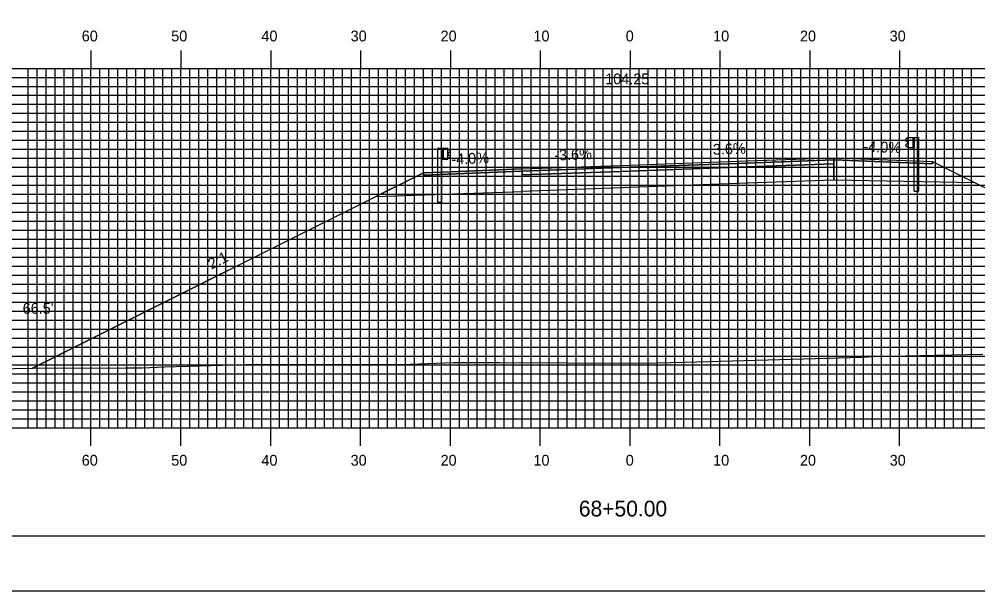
# Model space of a CAD drawing. Extents: x 1759823 to 1760167, y 442591 to 442811.
# Drawn here: x 1759921.2 to 1760027.9, y 442590.5 to 442654.1 of the extents above; entities that cross this region are included whole.
import ezdxf

# ---------------------------------------------------------------- set-up
doc = ezdxf.new("R2010")
doc.units = 0
for name, color, linetype in [('ANNOTATION', 7, 'Continuous'), ('BORDER', 7, 'Continuous'), ('D_Guardrail_Beam_Lt', 7, 'Continuous'), ('D_Guardrail_Beam_Rt', 7, 'Continuous'), ('D_Roadway_Centerline', 7, 'Continuous'), ('D_Roadway_Centerline_Text', 7, 'Continuous'), ('D_Roadway_Edge_Shoulder', 7, 'Continuous'), ('D_Roadway_Edge_TW', 7, 'Continuous'), ('D_Roadway_Pavement', 7, 'Continuous'), ('D_Roadway_SlopeLines', 7, 'Continuous'), ('D_Roadway_SubGrade', 7, 'Continuous'), ('D_Text_Standard', 7, 'Continuous'), ('H_V ANNOTATION', 7, 'Continuous'), ('MAJOR', 7, 'Continuous'), ('MINOR', 7, 'Continuous'), ('PLOT BOUNDARY', 7, 'Continuous'), ('S_Roadway_Centerline', 7, 'Continuous')]:
    doc.layers.add(name, color=color, linetype=linetype)

msp = doc.modelspace()

# ---------------------------------------------------------------- linework, layer by layer
at = {"layer": 'BORDER'}
msp.add_lwpolyline([(1759839.59, 442596.67), (1760159.59, 442596.67), (1760159.59, 442806.67), (1759839.59, 442806.67)], close=True, dxfattribs=at)
at = {"layer": 'D_Guardrail_Beam_Lt'}
for p, q in [((1759967.76, 442639.75), (1759967.76, 442633.75)), ((1759968.23, 442639.75), (1759967.76, 442639.75)), ((1759968.92, 442639.75), (1759968.23, 442639.75)), ((1759968.23, 442639.75), (1759968.23, 442638.58)), ((1759968.29, 442639.75), (1759968.29, 442638.58)), ((1759968.4, 442639.75), (1759968.4, 442638.58)), ((1759968.92, 442638.58), (1759968.92, 442639.75)), ((1759968.92, 442639.66), (1759968.99, 442639.65)), ((1759968.92, 442639.2), (1759968.92, 442639.13)), ((1759969.15, 442639.4), (1759968.95, 442639.26)), ((1759968.95, 442639.06), (1759969.15, 442638.93)), ((1759969.01, 442639.64), (1759969.15, 442639.54)), ((1759968.23, 442638.58), (1759968.92, 442638.58)), ((1759968.25, 442633.75), (1759968.25, 442638.58)), ((1759968.99, 442638.68), (1759968.92, 442638.66)), ((1759969.15, 442638.78), (1759969.01, 442638.68)), ((1759968.25, 442633.75), (1759967.76, 442633.75))]:
    msp.add_line(p, q, dxfattribs=at)
for centre, major_axis, start_param, end_param in [((1759969, 442639.2), (-0.0789, 0), 5.323254, 6.283185), ((1759969, 442639.13), (-0.0789, 0), 6.283185, 7.243116), ((1759968.98, 442639.61), (0.0417, 0), 0.959931, 1.376053), ((1759969.1, 442639.47), (0.0877, 0), 5.323254, 7.243116), ((1759968.98, 442638.72), (0.0417, 0), 4.907132, 5.323254), ((1759969.1, 442638.86), (0.0877, 0), 5.323254, 7.243116)]:
    msp.add_ellipse(centre, major_axis=major_axis, ratio=0.995501, start_param=start_param, end_param=end_param, dxfattribs=at)
at = {"layer": 'D_Guardrail_Beam_Rt'}
for p, q in [((1760020.04, 442640.89), (1760019.9, 442640.79)), ((1760019.9, 442640.65), (1760020.09, 442640.51)), ((1760020.09, 442640.31), (1760019.9, 442640.18)), ((1760020.13, 442640.91), (1760020.06, 442640.9)), ((1760020.13, 442640.99), (1760020.82, 442640.99)), ((1760020.13, 442639.83), (1760020.13, 442640.99)), ((1760020.13, 442640.45), (1760020.13, 442640.38)), ((1760020.65, 442640.99), (1760020.65, 442639.83)), ((1760020.76, 442640.99), (1760020.76, 442639.83)), ((1760020.82, 442640.99), (1760021.29, 442640.99)), ((1760020.82, 442640.99), (1760020.82, 442639.83)), ((1760021.29, 442640.99), (1760021.29, 442634.99)), ((1760019.9, 442640.03), (1760020.04, 442639.93)), ((1760020.06, 442639.93), (1760020.13, 442639.91)), ((1760020.82, 442639.83), (1760020.13, 442639.83)), ((1760020.8, 442634.99), (1760020.8, 442639.83)), ((1760020.8, 442634.99), (1760021.29, 442634.99))]:
    msp.add_line(p, q, dxfattribs=at)
for centre, major_axis, start_param, end_param in [((1760019.95, 442640.72), (-0.0877, 0), 5.323254, 7.243116), ((1760019.95, 442640.1), (-0.0877, 0), 5.323254, 7.243116), ((1760020.07, 442640.86), (-0.0417, 0), 4.907132, 5.323254), ((1760020.05, 442640.45), (0.0789, 0), 0, 0.959931), ((1760020.05, 442640.38), (0.0789, 0), 5.323254, 6.283185), ((1760020.07, 442639.97), (-0.0417, 0), 0.959931, 1.376053)]:
    msp.add_ellipse(centre, major_axis=major_axis, ratio=0.995501, start_param=start_param, end_param=end_param, dxfattribs=at)
at = {"layer": 'D_Roadway_Centerline'}
msp.add_lwpolyline([(1759922.69, 442615.3), (1759960.89, 442634.4), (1759966.19, 442637.04), (1759969.19, 442637.16), (1759977.19, 442637.48), (1759989.19, 442637.91), (1760001.19, 442638.35), (1760011.86, 442638.73), (1760019.86, 442638.41), (1760022.86, 442638.29), (1760027.61, 442635.92), (1760064.16, 442617.64)], dxfattribs=at)
at = {"layer": 'D_Roadway_Edge_Shoulder'}
for points in [[(1760011.86, 442638.73), (1760019.86, 442638.41), (1760019.86, 442638.41), (1760022.86, 442638.29), (1760022.86, 442638.04), (1760011.86, 442638.48)], [(1759977.19, 442637.48), (1759969.19, 442637.16), (1759969.19, 442637.16), (1759966.19, 442637.04), (1759966.19, 442636.79), (1759977.19, 442637.23)]]:
    msp.add_lwpolyline(points, close=True, dxfattribs=at)
at = {"layer": 'D_Roadway_Edge_TW'}
for points in [[(1759977.19, 442637.23), (1759977.19, 442637.48), (1759989.19, 442637.91), (1760001.19, 442638.35), (1760001.19, 442638.1), (1759989.19, 442637.66)], [(1760001.19, 442638.35), (1760011.86, 442638.73), (1760011.86, 442638.48), (1760001.19, 442638.1)]]:
    msp.add_lwpolyline(points, close=True, dxfattribs=at)
at = {"layer": 'D_Roadway_Pavement'}
for points in [[(1759977.19, 442636.82), (1759977.19, 442637.23), (1759989.19, 442637.66), (1760001.19, 442638.1), (1760001.19, 442637.68), (1759989.19, 442637.25)], [(1760001.19, 442638.1), (1760011.86, 442638.48), (1760011.86, 442638.06), (1760001.19, 442637.68)]]:
    msp.add_lwpolyline(points, close=True, dxfattribs=at)
for points in [[(1760011.86, 442638.48), (1760011.86, 442638.06)], [(1760011.86, 442638.48), (1760011.86, 442638.06)], [(1759977.19, 442637.23), (1759977.19, 442636.82)]]:
    msp.add_lwpolyline(points, dxfattribs=at)
at = {"layer": 'D_Roadway_SlopeLines'}
for points in [[(1760022.86, 442638.29), (1760064.16, 442617.64)], [(1759966.19, 442637.04), (1759922.69, 442615.3)]]:
    msp.add_lwpolyline(points, dxfattribs=at)
at = {"layer": 'D_Roadway_SubGrade'}
for points in [[(1760001.19, 442637.68), (1760011.86, 442638.06), (1760011.86, 442636.23), (1760001.19, 442635.85)], [(1760011.86, 442638.06), (1760011.86, 442638.48), (1760022.86, 442638.04), (1760022.86, 442638.29), (1760027.61, 442635.92), (1760011.86, 442636.23)], [(1759977.19, 442636.82), (1759977.19, 442637.23), (1759966.19, 442636.79), (1759966.19, 442637.04), (1759960.89, 442634.4), (1759977.19, 442634.98)], [(1759977.19, 442634.98), (1759977.19, 442636.82), (1759989.19, 442637.25), (1760001.19, 442637.68), (1760001.19, 442635.85), (1759989.19, 442635.41)]]:
    msp.add_lwpolyline(points, close=True, dxfattribs=at)
at = {"layer": 'MAJOR'}
for p, q in [((1759929.19, 442650.67), (1759929.19, 442648.67)), ((1759939.19, 442650.67), (1759939.19, 442648.67)), ((1759949.19, 442650.67), (1759949.19, 442648.67)), ((1759959.19, 442650.67), (1759959.19, 442648.67)), ((1759969.19, 442650.67), (1759969.19, 442648.67)), ((1759979.19, 442650.67), (1759979.19, 442648.67)), ((1759989.19, 442650.67), (1759989.19, 442648.67)), ((1759999.19, 442650.67), (1759999.19, 442648.67)), ((1760009.19, 442650.67), (1760009.19, 442648.67)), ((1760019.19, 442650.67), (1760019.19, 442648.67)), ((1759849.19, 442648.67), (1760129.19, 442648.67)), ((1759849.19, 442648.67), (1760129.19, 442648.67)), ((1759929.19, 442608.67), (1759929.19, 442648.67)), ((1759939.19, 442608.67), (1759939.19, 442648.67)), ((1759949.19, 442608.67), (1759949.19, 442648.67)), ((1759959.19, 442608.67), (1759959.19, 442648.67)), ((1759969.19, 442608.67), (1759969.19, 442648.67)), ((1759979.19, 442608.67), (1759979.19, 442648.67)), ((1759989.19, 442608.67), (1759989.19, 442648.67)), ((1759999.19, 442608.67), (1759999.19, 442648.67)), ((1760009.19, 442608.67), (1760009.19, 442648.67)), ((1760019.19, 442608.67), (1760019.19, 442648.67)), ((1759849.19, 442643.67), (1760129.19, 442643.67)), ((1759849.19, 442638.67), (1760129.19, 442638.67)), ((1759849.19, 442633.67), (1760129.19, 442633.67)), ((1759849.19, 442628.67), (1760129.19, 442628.67)), ((1759849.19, 442623.67), (1760129.19, 442623.67)), ((1759849.19, 442618.67), (1760129.19, 442618.67)), ((1759849.19, 442613.67), (1760129.19, 442613.67)), ((1759849.19, 442608.67), (1760129.19, 442608.67)), ((1759849.19, 442608.67), (1760129.19, 442608.67)), ((1759929.19, 442606.66), (1759929.19, 442608.67)), ((1759939.19, 442606.66), (1759939.19, 442608.67)), ((1759949.19, 442606.66), (1759949.19, 442608.67)), ((1759959.19, 442606.66), (1759959.19, 442608.67)), ((1759969.19, 442606.66), (1759969.19, 442608.67)), ((1759979.19, 442606.66), (1759979.19, 442608.67)), ((1759989.19, 442606.66), (1759989.19, 442608.67)), ((1759999.19, 442606.66), (1759999.19, 442608.67)), ((1760009.19, 442606.66), (1760009.19, 442608.67)), ((1760019.19, 442606.66), (1760019.19, 442608.67))]:
    msp.add_line(p, q, dxfattribs=at)
at = {"layer": 'MINOR'}
for p, q in [((1759922.19, 442608.67), (1759922.19, 442648.67)), ((1759923.19, 442608.67), (1759923.19, 442648.67)), ((1759924.19, 442608.67), (1759924.19, 442648.67)), ((1759925.19, 442608.67), (1759925.19, 442648.67)), ((1759926.19, 442608.67), (1759926.19, 442648.67)), ((1759927.19, 442608.67), (1759927.19, 442648.67)), ((1759928.19, 442608.67), (1759928.19, 442648.67)), ((1759930.19, 442608.67), (1759930.19, 442648.67)), ((1759931.19, 442608.67), (1759931.19, 442648.67)), ((1759932.19, 442608.67), (1759932.19, 442648.67)), ((1759933.19, 442608.67), (1759933.19, 442648.67)), ((1759934.19, 442608.67), (1759934.19, 442648.67)), ((1759935.19, 442608.67), (1759935.19, 442648.67)), ((1759936.19, 442608.67), (1759936.19, 442648.67)), ((1759937.19, 442608.67), (1759937.19, 442648.67)), ((1759938.19, 442608.67), (1759938.19, 442648.67)), ((1759940.19, 442608.67), (1759940.19, 442648.67)), ((1759941.19, 442608.67), (1759941.19, 442648.67)), ((1759942.19, 442608.67), (1759942.19, 442648.67)), ((1759943.19, 442608.67), (1759943.19, 442648.67)), ((1759944.19, 442608.67), (1759944.19, 442648.67)), ((1759945.19, 442608.67), (1759945.19, 442648.67)), ((1759946.19, 442608.67), (1759946.19, 442648.67)), ((1759947.19, 442608.67), (1759947.19, 442648.67)), ((1759948.19, 442608.67), (1759948.19, 442648.67)), ((1759950.19, 442608.67), (1759950.19, 442648.67)), ((1759951.19, 442608.67), (1759951.19, 442648.67)), ((1759952.19, 442608.67), (1759952.19, 442648.67)), ((1759953.19, 442608.67), (1759953.19, 442648.67)), ((1759954.19, 442608.67), (1759954.19, 442648.67)), ((1759955.19, 442608.67), (1759955.19, 442648.67)), ((1759956.19, 442608.67), (1759956.19, 442648.67)), ((1759957.19, 442608.67), (1759957.19, 442648.67)), ((1759958.19, 442608.67), (1759958.19, 442648.67)), ((1759960.19, 442608.67), (1759960.19, 442648.67)), ((1759961.19, 442608.67), (1759961.19, 442648.67)), ((1759962.19, 442608.67), (1759962.19, 442648.67)), ((1759963.19, 442608.67), (1759963.19, 442648.67)), ((1759964.19, 442608.67), (1759964.19, 442648.67)), ((1759965.19, 442608.67), (1759965.19, 442648.67)), ((1759966.19, 442608.67), (1759966.19, 442648.67)), ((1759967.19, 442608.67), (1759967.19, 442648.67)), ((1759968.19, 442608.67), (1759968.19, 442648.67)), ((1759970.19, 442608.67), (1759970.19, 442648.67)), ((1759971.19, 442608.67), (1759971.19, 442648.67)), ((1759972.19, 442608.67), (1759972.19, 442648.67)), ((1759973.19, 442608.67), (1759973.19, 442648.67)), ((1759974.19, 442608.67), (1759974.19, 442648.67)), ((1759975.19, 442608.67), (1759975.19, 442648.67)), ((1759976.19, 442608.67), (1759976.19, 442648.67)), ((1759977.19, 442608.67), (1759977.19, 442648.67)), ((1759978.19, 442608.67), (1759978.19, 442648.67)), ((1759980.19, 442608.67), (1759980.19, 442648.67)), ((1759981.19, 442608.67), (1759981.19, 442648.67)), ((1759982.19, 442608.67), (1759982.19, 442648.67)), ((1759983.19, 442608.67), (1759983.19, 442648.67)), ((1759984.19, 442608.67), (1759984.19, 442648.67)), ((1759985.19, 442608.67), (1759985.19, 442648.67)), ((1759986.19, 442608.67), (1759986.19, 442648.67)), ((1759987.19, 442608.67), (1759987.19, 442648.67)), ((1759988.19, 442608.67), (1759988.19, 442648.67)), ((1759990.19, 442608.67), (1759990.19, 442648.67)), ((1759991.19, 442608.67), (1759991.19, 442648.67)), ((1759992.19, 442608.67), (1759992.19, 442648.67)), ((1759993.19, 442608.67), (1759993.19, 442648.67)), ((1759994.19, 442608.67), (1759994.19, 442648.67)), ((1759995.19, 442608.67), (1759995.19, 442648.67)), ((1759996.19, 442608.67), (1759996.19, 442648.67)), ((1759997.19, 442608.67), (1759997.19, 442648.67)), ((1759998.19, 442608.67), (1759998.19, 442648.67)), ((1760000.19, 442608.67), (1760000.19, 442648.67)), ((1760001.19, 442608.67), (1760001.19, 442648.67)), ((1760002.19, 442608.67), (1760002.19, 442648.67)), ((1760003.19, 442608.67), (1760003.19, 442648.67)), ((1760004.19, 442608.67), (1760004.19, 442648.67)), ((1760005.19, 442608.67), (1760005.19, 442648.67)), ((1760006.19, 442608.67), (1760006.19, 442648.67)), ((1760007.19, 442608.67), (1760007.19, 442648.67)), ((1760008.19, 442608.67), (1760008.19, 442648.67)), ((1760010.19, 442608.67), (1760010.19, 442648.67)), ((1760011.19, 442608.67), (1760011.19, 442648.67)), ((1760012.19, 442608.67), (1760012.19, 442648.67)), ((1760013.19, 442608.67), (1760013.19, 442648.67)), ((1760014.19, 442608.67), (1760014.19, 442648.67)), ((1760015.19, 442608.67), (1760015.19, 442648.67)), ((1760016.19, 442608.67), (1760016.19, 442648.67)), ((1760017.19, 442608.67), (1760017.19, 442648.67)), ((1760018.19, 442608.67), (1760018.19, 442648.67)), ((1760020.19, 442608.67), (1760020.19, 442648.67)), ((1760021.19, 442608.67), (1760021.19, 442648.67)), ((1760022.19, 442608.67), (1760022.19, 442648.67)), ((1760023.19, 442608.67), (1760023.19, 442648.67)), ((1760024.19, 442608.67), (1760024.19, 442648.67)), ((1760025.19, 442608.67), (1760025.19, 442648.67)), ((1760026.19, 442608.67), (1760026.19, 442648.67)), ((1760027.19, 442608.67), (1760027.19, 442648.67)), ((1759849.19, 442647.67), (1760129.19, 442647.67)), ((1759849.19, 442646.67), (1760129.19, 442646.67)), ((1759849.19, 442645.67), (1760129.19, 442645.67)), ((1759849.19, 442644.67), (1760129.19, 442644.67)), ((1759849.19, 442642.67), (1760129.19, 442642.67)), ((1759849.19, 442641.67), (1760129.19, 442641.67)), ((1759849.19, 442640.67), (1760129.19, 442640.67)), ((1759849.19, 442639.67), (1760129.19, 442639.67)), ((1759849.19, 442637.67), (1760129.19, 442637.67)), ((1759849.19, 442636.67), (1760129.19, 442636.67)), ((1759849.19, 442635.67), (1760129.19, 442635.67)), ((1759849.19, 442634.67), (1760129.19, 442634.67)), ((1759849.19, 442632.67), (1760129.19, 442632.67)), ((1759849.19, 442631.67), (1760129.19, 442631.67)), ((1759849.19, 442630.67), (1760129.19, 442630.67)), ((1759849.19, 442629.67), (1760129.19, 442629.67)), ((1759849.19, 442627.67), (1760129.19, 442627.67)), ((1759849.19, 442626.67), (1760129.19, 442626.67)), ((1759849.19, 442625.67), (1760129.19, 442625.67)), ((1759849.19, 442624.67), (1760129.19, 442624.67)), ((1759849.19, 442622.67), (1760129.19, 442622.67)), ((1759849.19, 442621.67), (1760129.19, 442621.67)), ((1759849.19, 442620.67), (1760129.19, 442620.67)), ((1759849.19, 442619.67), (1760129.19, 442619.67)), ((1759849.19, 442617.67), (1760129.19, 442617.67)), ((1759849.19, 442616.67), (1760129.19, 442616.67)), ((1759849.19, 442615.67), (1760129.19, 442615.67)), ((1759849.19, 442614.67), (1760129.19, 442614.67)), ((1759849.19, 442612.67), (1760129.19, 442612.67)), ((1759849.19, 442611.67), (1760129.19, 442611.67)), ((1759849.19, 442610.67), (1760129.19, 442610.67)), ((1759849.19, 442609.67), (1760129.19, 442609.67))]:
    msp.add_line(p, q, dxfattribs=at)
at = {"layer": 'PLOT BOUNDARY'}
msp.add_lwpolyline([(1759823.4, 442590.55), (1760163.4, 442590.55), (1760163.4, 442810.55), (1759823.4, 442810.55)], close=True, dxfattribs=at)
at = {"layer": 'S_Roadway_Centerline'}
msp.add_lwpolyline([(1759912.12, 442615.12), (1759922.73, 442615.3), (1759933.02, 442615.34), (1759934.89, 442615.34), (1759937.4, 442615.46), (1759947.64, 442615.77), (1759954.97, 442615.73), (1759963.75, 442615.71), (1759969.55, 442615.93), (1759974.66, 442615.94), (1759982.12, 442615.92), (1759990.64, 442615.88), (1759995.28, 442615.97), (1760007.18, 442616.31), (1760014.98, 442616.55), (1760016.28, 442616.62), (1760018.12, 442616.64), (1760028.47, 442616.89)], dxfattribs=at)

# ---------------------------------------------------------------- texts
at = {"layer": 'ANNOTATION'}
for s, rotation, p in [('3.6%', 2.0618, (1759998.43, 442639.05)), ('-4.0%', 357.7094, (1760015.15, 442639.4)), ('-4.0%', 2.2906, (1759969.32, 442637.97)), ('-3.6%', 2.0618, (1759980.77, 442638.41)), ('2:1', 26.5651, (1759942.59, 442626.28))]:
    msp.add_text(s, height=1.2, rotation=rotation, dxfattribs=at).set_placement(p)
at = {"layer": 'D_Roadway_Centerline'}
for s, p in [('C', (1759989.18, 442637.91)), ('L', (1759989.19, 442637.91))]:
    msp.add_text(s, height=0.0146, dxfattribs=at).set_placement(p)
at = {"layer": 'D_Roadway_Centerline_Text'}
msp.add_text('104.25', height=1.2, dxfattribs=at).set_placement((1759986.43, 442646.9))
at = {"layer": 'D_Text_Standard'}
msp.add_text("66.5'", height=1.2, dxfattribs=at).set_placement((1759921.59, 442621.37))
at = {"layer": 'H_V ANNOTATION'}
for s, height, p in [('60', 1.2, (1759928.16, 442651.67)), ('50', 1.2, (1759938.12, 442651.67)), ('40', 1.2, (1759948.16, 442651.67)), ('30', 1.2, (1759958.09, 442651.67)), ('20', 1.2, (1759968.1, 442651.67)), ('10', 1.2, (1759978.44, 442651.67)), ('0', 1.2, (1759988.71, 442651.67)), ('10', 1.2, (1759998.44, 442651.67)), ('20', 1.2, (1760008.1, 442651.67)), ('30', 1.2, (1760018.09, 442651.67)), ('60', 1.2, (1759928.16, 442604.47)), ('50', 1.2, (1759938.12, 442604.47)), ('40', 1.2, (1759948.16, 442604.47)), ('30', 1.2, (1759958.09, 442604.47)), ('20', 1.2, (1759968.1, 442604.47)), ('10', 1.2, (1759978.44, 442604.47)), ('0', 1.2, (1759988.71, 442604.47)), ('10', 1.2, (1759998.44, 442604.47)), ('20', 1.2, (1760008.1, 442604.47)), ('30', 1.2, (1760018.09, 442604.47)), ('68+50.00', 1.75, (1759983.49, 442598.82))]:
    msp.add_text(s, height=height, dxfattribs=at).set_placement(p)

doc.saveas('drawing.dxf')
